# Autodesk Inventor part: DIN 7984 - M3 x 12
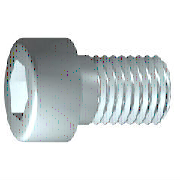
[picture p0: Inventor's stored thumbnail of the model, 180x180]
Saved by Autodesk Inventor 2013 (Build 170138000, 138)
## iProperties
Created: 2012-02
Part Number: DIN 7984 - M3 x 12
Material: Stahl, weich
Description: Zylinderkopfschraube
Document SubType Name: Modeling
Standard: DIN 7984
Designer: rYan
Standard Revision: 1985
Standards Organization: DIN
Language: de-DE
Size Designation: M3 x 12
Categories: <MemberInstance><Categories><Category DisplayName="Verbindungselemente" InternalName="e4da775c-781d-43d5-af7c-5136215cf5a6" Mnemonic="FSTN"><Category DisplayNam
Density: 7.86 g/cm^3
Mass: 0.986587 g
Surface Area: 2.02025 cm^2
Volume: 0.12552 cm^3
IsCustomPart: 0
Author: rYan
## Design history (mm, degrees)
sketch "Skizze1"
  geometry: L1 (0.167, 0)-(12, 0); L2 (12, 0)-(12, 1.5); L3 (12, 1.5)-(1.5, 1.5); L4 (1.5, 1.5)-(1.193, 1.5); L5 (1.193, 1.5)-(0, 1.5); L6 (0, 1.5)-(0, 2.75); L7 (0, 2.75)-(-2, 2.75); L8 (-2, 2.75)-(-2, 1.155); L9 (-2, 1.155)-(-0.5, 1.155); L10 (-0.5, 1.155)-(0.167, 0); L11 (-4.8, 0)-(14.8, 0) reference; L12 (0, -0.55)-(0, 3.3) reference; L13 (1.5, 1.5)-(0, 1.5)
  constraints: 22 end point, 6 parallel, 2 collinear, 2 perpendicular, 1 horizontal, 1 point on line
  dimensions: "d1" = 10.5 distance from line of L3.end L2 (= GEL); "d2" = 0.30683 distance of L4.end L3.end (computed from GAL); "d3" = 2 distance between parallel lines of L8 L6 (= KOH); "d4" = 1.5 distance of L8.end L9.end (= INTI); "d5" = 60 deg angle of L10 L1; "d6" = 3 diameter of L3 L1 (= GD); "d7" = 3 diameter of L5 L1 (= BDM); "d8" = 2.3094 diameter of L9 L1 (= 1.1547 x SW); "d9" = 5.5 diameter of L7 L1 (= KOD); "d26" = 12 distance between parallel lines of L12 L2 (= NLG)
revolve "Körper" sketch "Skizze1" stored, may be unused: angle "d10" = 90 deg
sketch "Skizze2"
  geometry: L1 (0, -3.85)-(0, 3.85) reference; L2 (-3.85, 0)-(3.85, 0) reference; L3 (1.155, 0)-(0.577, -1); L4 (0.577, -1)-(-0.577, -1); L5 (-0.577, -1)-(-1.155, 0); L6 (-1.155, 0)-(-0.577, 1); L7 (-0.577, 1)-(0.577, 1); L8 (0.577, 1)-(1.155, 0); 2 further points
  constraints: 12 end point, 1 coincident, 1 horizontal alignment, 1 point on line, 12 other
extrude "Loch" join sketch "Skizze2" stored distance "d11" = 10; taper "d12" = 0 deg
workplane "Work Plane1"
fillet "Fillet2" dims "d30" = 0.1 (= R)
body "Solid1"
fillet "Rundung1" dims "d17" = 0.3 (= RR)
feature "Gewinde" dims "d13" = 10.5 (= GEL), "d14" = 0
chamfer "Fase1" distance "d15" = 0.30673 (= -0.5 x SPD + 0.5 x GD); stored, may be unused: second distance "d16" = 0.30673 (= GUL), angle "d27" = 45 deg
other parameters: "GD" = 3 (= NND) [user parameter; used in 2 equation terms], "NLG" = 12 [user parameter; used in 1 equation term], "GEL" = 10.5 [user parameter; used in 2 equation terms], "KOD" = 5.5 [user parameter; used in 1 equation term], "KOH" = 2 [user parameter; used in 1 equation term], "INTI" = 1.5 [user parameter; used in 1 equation term], "GAL" = 0.30673 (= 0.61345 x PTC) [user parameter; used in 1 equation term], "GUL" = 0.30673 (= 0.61345 x PTC) [user parameter; used in 1 equation term], "BDM" = 3 (= NND) [user parameter; used in 1 equation term], "SW" = 2 [user parameter; used in 2 equation terms], "RR" = 0.3 [user parameter; used in 1 equation term], "SPD" = 2.38655 (= NND - 1.2269 x PTC) [user parameter; used in 1 equation term], "d19" = 0, "d28" = 0, "d29" = 0, "R" = 0.1 [user parameter; used in 1 equation term], "TOA" = 30 deg [user parameter], "GD1" = 2.38655 (= THREADDIA - 1.2269 x PTC) [user parameter], "THREADDIA" = 3 [user parameter; used in 1 equation term], "FAWI" = 45 deg [user parameter], "ANG" = 120 deg [user parameter], "PTC" = 0.5 [user parameter; used in 5 equation terms], "NND" = 3 [user parameter; used in 3 equation terms], "E0" = 2.31 (= 1.155 x SW) [user parameter]
